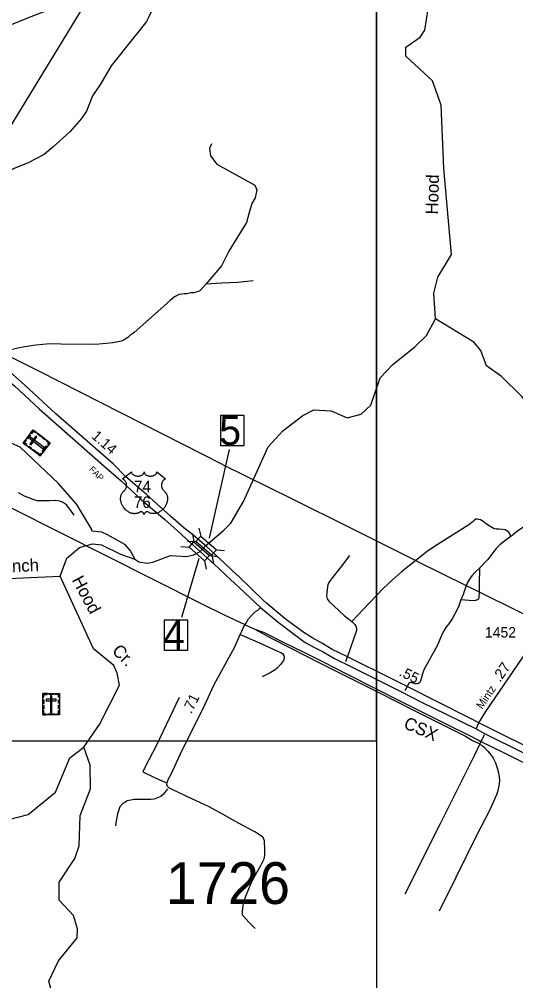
# Model space of a CAD drawing. Extents: x 2225501 to 2309677, y 165449 to 227696.
# Drawn here: x 2261977 to 2267922, y 188364 to 199877 of the extents above; entities that cross this region are included whole.
import ezdxf

# ---------------------------------------------------------------- set-up
doc = ezdxf.new("R2010")
doc.units = 0
for name, color, linetype in [('Black Area Fill Shapes', 7, 'Continuous'), ('E_RDY_CMT_EOP', 7, 'Continuous'), ('MARK ENDS WORD SYMBOL CELL', 7, 'Continuous'), ('Old_Level_3', 7, 'Continuous'), ('Old_Level_33', 7, 'Continuous'), ('Old_Level_41', 7, 'Continuous'), ('Old_Level_46', 7, 'Continuous'), ('P_HYD_Ditch_Flow_Line', 7, 'Continuous'), ('P_HYD_Endwall_838_01_48_Dia_Single_CELL', 7, 'Continuous'), ('P_HYD_Pipe_Flowable_Fill', 7, 'Continuous'), ('P_HYD_Pipe_Pipe_Removal', 7, 'Continuous'), ('P_HYD_RIP_RAP_LABEL', 7, 'Continuous'), ('P_HYD_RipRap_Pad_876_02_18in_Outlet_With_Ditch-Top_CELL', 7, 'Continuous'), ('P_HYD_RipRap_Pad_876_02_36in_Outlet_With_Ditch-Top_CELL', 7, 'Continuous'), ('P_HYD_RipRap_Pad_876_02_36in_Outlet_With_Ditch_CELL', 7, 'Continuous'), ('P_RDY_Dimension_Text', 7, 'Continuous'), ('Prop Mkg Solid Yellow Edge Line', 7, 'Continuous'), ('Prop Support', 7, 'Continuous'), ('Raster_Level_0', 7, 'Continuous'), ('Scratch_Level_1', 7, 'Continuous'), ('Scratch_Level_2', 7, 'Continuous'), ('Typical Terminator CELL', 7, 'Continuous')]:
    doc.layers.add(name, color=color, linetype=linetype)

msp = doc.modelspace()

# ---------------------------------------------------------------- linework, layer by layer
at = {"layer": 'Black Area Fill Shapes'}
for p, q in [((2267328, 193098), (2267482, 193022)), ((2264683, 192627), (2264797, 192573))]:
    msp.add_line(p, q, dxfattribs=at)
for points in [[(2262843, 200185), (2262115, 199905), (2260829, 199388), (2259311, 198774), (2259155, 198714)], [(2264419, 194543), (2262221, 195661), (2261765, 195888)], [(2264683, 192627), (2264436, 192743), (2264161, 192876), (2259628, 195156)], [(2264420, 194540), (2265246, 194134), (2265934, 193792), (2266724, 193397)], [(2266724, 193397), (2266754, 193381), (2267328, 193098)], [(2267482, 193022), (2267541, 192993), (2268273, 192629)], [(2264797, 192573), (2265002, 192462), (2265244, 192337), (2265570, 192172), (2265890, 192010), (2266276, 191818), (2266712, 191596), (2267153, 191375), (2267318, 191291), (2267404, 191240), (2267491, 191200)], [(2267491, 191200), (2267492, 191199), (2267519, 191182), (2267539, 191165), (2267588, 191112), (2267623, 191070), (2267651, 191031), (2267679, 190973), (2267700, 190913), (2267715, 190855), (2267724, 190801), (2267726, 190765), (2267723, 190722), (2267717, 190683), (2267707, 190641), (2267694, 190599), (2267676, 190553), (2267644, 190481), (2267610, 190412), (2267448, 190094), (2267204, 189599), (2267004, 189199)]]:
    msp.add_lwpolyline(points, dxfattribs=at)
at = {"layer": 'Old_Level_3'}
for p, q in [((2265887, 192195), (2265883, 192183)), ((2265906, 192248), (2265887, 192195)), ((2266601, 191851), (2266593, 191838)), ((2266627, 191897), (2266601, 191851)), ((2267514, 191249), (2267505, 191230)), ((2267539, 191301), (2267514, 191249)), ((2267543, 191310), (2267539, 191301)), ((2267505, 191230), (2267491, 191200))]:
    msp.add_line(p, q, dxfattribs=at)
for points in [[(2264023, 200510), (2263878, 200419), (2263792, 200372), (2263758, 200346), (2263715, 200289), (2263654, 200179), (2263615, 200085), (2263530, 199908), (2263499, 199852), (2263428, 199760)], [(2263428, 199760), (2263330, 199633), (2263077, 199319), (2262951, 199100), (2262856, 198961), (2262782, 198776), (2262724, 198690), (2262584, 198529), (2262379, 198345), (2262276, 198256), (2262075, 198153), (2261923, 198094), (2261854, 198057), (2261784, 198017), (2261729, 197970), (2261689, 197924), (2261620, 197799), (2261558, 197711)], [(2264279, 198386), (2264256, 198328), (2264267, 198240), (2264343, 198141), (2264797, 197891), (2264820, 197833), (2264802, 197740), (2264762, 197670), (2264727, 197548), (2264698, 197443), (2264488, 197100), (2264398, 196924), (2264214, 196709)], [(2264214, 196709), (2264139, 196626), (2264123, 196618), (2264069, 196600), (2264033, 196600), (2263983, 196589), (2263955, 196589), (2263893, 196580), (2263837, 196552), (2263786, 196511), (2263351, 196124), (2263301, 196090), (2263277, 196068), (2263232, 196037), (2263200, 196021), (2263098, 196002), (2262894, 195982), (2262476, 195985), (2262345, 195990), (2262175, 195976), (2262045, 195955), (2261961, 195939), (2261835, 195908), (2261765, 195888)], [(2264214, 196709), (2264404, 196720), (2264593, 196728), (2264777, 196749)], [(2262635, 193941), (2262570, 194028), (2262542, 194062), (2262494, 194096), (2262458, 194108), (2262414, 194113), (2262338, 194109), (2262192, 194111), (2262144, 194127), (2262039, 194168), (2261967, 194206)], [(2267863, 193685), (2267848, 193725), (2267832, 193743), (2267816, 193753), (2267796, 193762), (2267765, 193767), (2267723, 193771), (2267687, 193770), (2267665, 193774), (2267595, 193816), (2267521, 193870), (2267498, 193885), (2267459, 193890), (2267445, 193890), (2267427, 193881), (2267410, 193863), (2267361, 193822), (2266947, 193563), (2266860, 193505), (2266724, 193397)], [(2268161, 193870), (2268092, 193839), (2268007, 193792), (2267942, 193749), (2267863, 193685)], [(2267863, 193685), (2267806, 193644), (2267733, 193585), (2267687, 193540), (2267584, 193406), (2267486, 193303)], [(2265933, 193458), (2265821, 193309), (2265710, 193171), (2265688, 193138), (2265673, 193107), (2265662, 193050), (2265655, 192976), (2265658, 192954), (2265664, 192937), (2265682, 192911), (2265869, 192738), (2265961, 192666)], [(2266724, 193397), (2266552, 193260), (2266446, 193166), (2266334, 193062), (2266094, 192810), (2265961, 192666)], [(2267486, 193303), (2267434, 193255), (2267395, 193212), (2267368, 193172), (2267344, 193132), (2267328, 193098)], [(2267486, 193303), (2267485, 193120), (2267482, 193022)], [(2267328, 193098), (2267322, 193085), (2267291, 192991), (2267264, 192925)], [(2267482, 193022), (2267480, 192949), (2267476, 192932), (2267462, 192924), (2267438, 192918), (2267412, 192915), (2267264, 192925)], [(2267264, 192925), (2267239, 192854), (2267213, 192794), (2267162, 192697), (2267129, 192648), (2267086, 192593), (2267061, 192555), (2267039, 192517), (2266986, 192384), (2266821, 192087), (2266804, 192041), (2266781, 191952), (2266773, 191936), (2266756, 191922), (2266740, 191920), (2266718, 191921), (2266666, 191936), (2266646, 191930), (2266627, 191897)], [(2265961, 192666), (2265993, 192632), (2266008, 192609), (2266014, 192587), (2266014, 192559), (2265906, 192248)], [(2264621, 192512), (2264853, 192412), (2265069, 192310), (2265110, 192294), (2265129, 192281), (2265143, 192259), (2265150, 192240), (2265150, 192228), (2265139, 192200), (2265106, 192153), (2265070, 192110), (2265041, 192087), (2264982, 192051), (2264886, 192005)], [(2263892, 191754), (2263619, 191187), (2263482, 190919), (2263456, 190867), (2263598, 190797), (2263733, 190739)], [(2267491, 191200), (2267423, 191057), (2267243, 190700), (2267017, 190242), (2266592, 189401)], [(2263751, 190661), (2263704, 190599), (2263672, 190571), (2263592, 190538), (2263554, 190536), (2263352, 190534), (2263271, 190520), (2263243, 190497), (2263219, 190487), (2263181, 190447), (2263152, 190363), (2263137, 190279), (2263131, 190221)], [(2264800, 188991), (2264728, 189062), (2264651, 189149), (2264651, 189192), (2264654, 189230), (2264663, 189294), (2264689, 189378), (2264733, 189486), (2264770, 189568), (2264869, 189745), (2264910, 189824), (2264916, 189870), (2264916, 189937), (2264914, 190040)]]:
    msp.add_lwpolyline(points, dxfattribs=at)
at = {"layer": 'Old_Level_33'}
for points in [[(2264914, 190040), (2264896, 190079), (2264878, 190095), (2264799, 190147), (2264557, 190275), (2264456, 190335), (2264250, 190448), (2264045, 190544), (2263808, 190654), (2263770, 190674), (2263751, 190691), (2263746, 190716), (2263750, 190738), (2263765, 190781), (2263796, 190839), (2263905, 191073), (2264198, 191667), (2264310, 191912), (2264441, 192153), (2264557, 192363), (2264621, 192512), (2264643, 192551), (2264668, 192606), (2264688, 192643), (2264723, 192696), (2264761, 192741), (2264807, 192785), (2264833, 192803), (2264867, 192835)], [(2267478, 191453), (2267564, 191588), (2268227, 192557), (2268238, 192574), (2268262, 192614), (2268273, 192629)], [(2267446, 191381), (2267478, 191453)]]:
    msp.add_lwpolyline(points, dxfattribs=at)
at = {"layer": 'Old_Level_41'}
msp.add_lwpolyline([(2264797, 192573), (2264855, 192556), (2264881, 192548), (2264917, 192531), (2265153, 192412), (2265368, 192306), (2265614, 192185), (2265897, 192040), (2266233, 191868), (2266549, 191708), (2266815, 191575), (2267126, 191420), (2267344, 191313), (2267483, 191241), (2267505, 191230), (2267760, 191104), (2268233, 190867)], dxfattribs=at)
at = {"layer": 'Old_Level_46'}
for points in [[(2264218, 193562), (2264055, 193705), (2263947, 193788), (2263787, 193927), (2263500, 194185), (2263249, 194403), (2263106, 194549), (2262416, 195153), (2262043, 195497), (2261860, 195659), (2261615, 195862), (2261559, 195902), (2261462, 195966), (2261288, 196067), (2261080, 196147), (2260943, 196189), (2260766, 196223), (2260631, 196248), (2260380, 196284), (2260177, 196311)], [(2260129, 196210), (2260183, 196202), (2260349, 196183), (2260525, 196155), (2260708, 196126), (2260872, 196091), (2261053, 196047), (2261233, 195984), (2261408, 195889), (2261522, 195818), (2261758, 195618), (2261921, 195486), (2262216, 195211), (2262991, 194529), (2263196, 194349), (2263442, 194123), (2263721, 193887), (2263873, 193751), (2263970, 193660), (2264145, 193503)], [(2264938, 192884), (2264897, 192923), (2264609, 193200), (2264531, 193274), (2264434, 193364), (2264218, 193562)], [(2264145, 193503), (2264361, 193306), (2264453, 193218), (2264611, 193074), (2264867, 192835)], [(2267478, 191453), (2267395, 191496), (2266944, 191725), (2266686, 191854), (2266469, 191962), (2265892, 192249), (2265723, 192332), (2265608, 192402), (2265491, 192466), (2265386, 192535), (2265268, 192617), (2265159, 192696), (2264938, 192884)], [(2264867, 192835), (2265076, 192657), (2265257, 192521), (2265401, 192416), (2265514, 192355), (2265616, 192302), (2265753, 192223), (2265947, 192127), (2266537, 191830), (2266800, 191697), (2267088, 191555), (2267446, 191381)], [(2267446, 191381), (2267549, 191323), (2268023, 191089), (2268853, 190675), (2269145, 190533), (2269376, 190413), (2269867, 190171), (2270152, 190029), (2270264, 189970), (2270773, 189716), (2271345, 189429), (2271616, 189294), (2272532, 188836)], [(2272571, 188913), (2271872, 189261), (2271516, 189439), (2271065, 189667), (2270762, 189820), (2270313, 190042), (2269837, 190283), (2269384, 190510), (2268843, 190777), (2268116, 191138), (2267673, 191357), (2267478, 191453)]]:
    msp.add_lwpolyline(points, dxfattribs=at)
at = {"layer": 'P_HYD_Endwall_838_01_48_Dia_Single_CELL'}
msp.add_lwpolyline([(2262842, 200192), (2261366, 197773), (2261577, 197678), (2260763, 196442), (2260802, 196385), (2260862, 196311), (2260866, 196277), (2260818, 196274), (2260687, 196341), (2260590, 196381), (2260485, 196410), (2260197, 196443), (2259793, 196486), (2259225, 196552), (2258394, 196652), (2257678, 196732), (2257280, 196779), (2256996, 196809), (2256790, 196892), (2256494, 197039)], dxfattribs=at)
at = {"layer": 'P_HYD_Pipe_Pipe_Removal'}
for points in [[(2243856, 191238), (2266254, 191238), (2266254, 223234), (2243856, 223234)], [(2266254, 165449), (2309677, 165449), (2309677, 209697), (2266254, 209697)]]:
    msp.add_lwpolyline(points, close=True, dxfattribs=at)
at = {"layer": 'P_HYD_RIP_RAP_LABEL'}
for p, q in [((2264254, 193662), (2264494, 194727)), ((2264129, 193422), (2263920, 192715))]:
    msp.add_line(p, q, dxfattribs=at)
for points in [[(2264390, 195136), (2264665, 195136), (2264665, 194768), (2264390, 194768)], [(2263717, 192686), (2263993, 192686), (2263993, 192318), (2263717, 192318)]]:
    msp.add_lwpolyline(points, close=True, dxfattribs=at)
at = {"layer": 'P_HYD_RipRap_Pad_876_02_18in_Outlet_With_Ditch-Top_CELL'}
msp.add_lwpolyline([(2263320, 194458), (2263320, 194454), (2263321, 194449), (2263322, 194446), (2263324, 194441), (2263328, 194435), (2263334, 194429), (2263340, 194424), (2263344, 194421), (2263352, 194417), (2263360, 194413), (2263369, 194411), (2263378, 194409), (2263389, 194408), (2263399, 194408), (2263410, 194408), (2263422, 194411), (2263427, 194412), (2263433, 194414), (2263439, 194417), (2263446, 194420), (2263451, 194423), (2263455, 194426), (2263460, 194432), (2263465, 194437), (2263467, 194440), (2263468, 194443), (2263471, 194450), (2263471, 194453), (2263472, 194459), (2263472, 194454), (2263472, 194450), (2263473, 194447), (2263475, 194444), (2263477, 194440), (2263479, 194436), (2263484, 194430), (2263487, 194428), (2263490, 194425), (2263497, 194420), (2263505, 194416), (2263510, 194414), (2263514, 194413), (2263519, 194411), (2263525, 194410), (2263530, 194409), (2263536, 194408), (2263542, 194408), (2263546, 194408), (2263552, 194408), (2263558, 194408), (2263563, 194409), (2263569, 194410), (2263574, 194411), (2263580, 194412), (2263586, 194414), (2263591, 194417), (2263598, 194420), (2263603, 194423), (2263607, 194427), (2263612, 194431), (2263616, 194436), (2263619, 194440), (2263620, 194443), (2263622, 194447), (2263623, 194452), (2263624, 194455), (2263624, 194459), (2263730, 194374), (2263727, 194373), (2263722, 194370), (2263717, 194367), (2263710, 194362), (2263707, 194359), (2263704, 194357), (2263701, 194353), (2263698, 194350), (2263695, 194346), (2263692, 194342), (2263690, 194337), (2263688, 194333), (2263684, 194325), (2263683, 194319), (2263682, 194315), (2263680, 194305), (2263680, 194301), (2263680, 194296), (2263680, 194291), (2263681, 194287), (2263682, 194282), (2263682, 194278), (2263684, 194273), (2263686, 194267), (2263688, 194261), (2263693, 194252), (2263699, 194243), (2263704, 194237), (2263708, 194233), (2263714, 194227), (2263718, 194224), (2263722, 194220), (2263729, 194212), (2263731, 194209), (2263734, 194205), (2263737, 194200), (2263739, 194196), (2263741, 194192), (2263745, 194183), (2263748, 194174), (2263749, 194169), (2263751, 194159), (2263752, 194154), (2263752, 194144), (2263753, 194131), (2263752, 194120), (2263749, 194106), (2263748, 194098), (2263745, 194088), (2263742, 194080), (2263737, 194068), (2263733, 194059), (2263727, 194049), (2263723, 194043), (2263719, 194036), (2263713, 194028), (2263707, 194020), (2263699, 194012), (2263693, 194005), (2263684, 193998), (2263679, 193994), (2263672, 193988), (2263662, 193982), (2263653, 193976), (2263645, 193972), (2263637, 193969), (2263628, 193965), (2263612, 193961), (2263606, 193960), (2263600, 193959), (2263593, 193958), (2263587, 193958), (2263579, 193958), (2263571, 193958), (2263563, 193960), (2263555, 193961), (2263546, 193964), (2263539, 193967), (2263531, 193971), (2263518, 193979), (2263514, 193981), (2263512, 193981), (2263507, 193982), (2263502, 193981), (2263497, 193979), (2263494, 193977), (2263490, 193975), (2263487, 193972), (2263484, 193969), (2263481, 193966), (2263479, 193964), (2263475, 193958), (2263474, 193955), (2263473, 193951), (2263471, 193946), (2263470, 193953), (2263468, 193957), (2263466, 193961), (2263463, 193964), (2263460, 193969), (2263456, 193972), (2263452, 193975), (2263448, 193978), (2263445, 193979), (2263441, 193981), (2263438, 193982), (2263434, 193982), (2263432, 193982), (2263428, 193981), (2263423, 193977), (2263419, 193974), (2263414, 193971), (2263408, 193968), (2263404, 193966), (2263399, 193964), (2263393, 193962), (2263386, 193960), (2263379, 193959), (2263373, 193958), (2263367, 193958), (2263361, 193957), (2263355, 193957), (2263350, 193958), (2263343, 193958), (2263335, 193960), (2263329, 193961), (2263322, 193963), (2263314, 193965), (2263307, 193968), (2263297, 193972), (2263290, 193976), (2263280, 193982), (2263267, 193991), (2263258, 193998), (2263251, 194004), (2263241, 194015), (2263235, 194021), (2263226, 194033), (2263220, 194042), (2263216, 194049), (2263210, 194059), (2263207, 194065), (2263203, 194075), (2263200, 194083), (2263197, 194092), (2263196, 194097), (2263194, 194106), (2263193, 194112), (2263191, 194121), (2263191, 194131), (2263191, 194139), (2263191, 194146), (2263192, 194155), (2263193, 194163), (2263195, 194171), (2263196, 194177), (2263199, 194183), (2263202, 194191), (2263205, 194198), (2263208, 194203), (2263213, 194210), (2263217, 194215), (2263222, 194221), (2263228, 194226), (2263233, 194231), (2263239, 194237), (2263242, 194240), (2263246, 194245), (2263249, 194250), (2263252, 194254), (2263255, 194260), (2263257, 194265), (2263259, 194272), (2263261, 194277), (2263262, 194284), (2263263, 194290), (2263263, 194297), (2263263, 194304), (2263262, 194311), (2263261, 194318), (2263259, 194324), (2263256, 194331), (2263254, 194336), (2263250, 194343), (2263245, 194350), (2263241, 194355), (2263236, 194360), (2263231, 194363), (2263227, 194366), (2263222, 194370), (2263217, 194372), (2263213, 194374)], close=True, dxfattribs=at)
at = {"layer": 'P_HYD_RipRap_Pad_876_02_36in_Outlet_With_Ditch-Top_CELL'}
msp.add_lwpolyline([(2262842, 200192), (2261366, 197773), (2261577, 197678), (2260763, 196442), (2260802, 196385), (2260862, 196311), (2260866, 196277), (2260818, 196274), (2260687, 196341), (2260590, 196381), (2260485, 196410), (2260197, 196443), (2259793, 196486), (2259225, 196552), (2258394, 196652), (2257678, 196732), (2257280, 196779), (2256996, 196809), (2256790, 196892), (2256494, 197039)], dxfattribs=at)
at = {"layer": 'P_HYD_RipRap_Pad_876_02_36in_Outlet_With_Ditch_CELL'}
for p, q in [((2264129, 193785), (2264150, 193687)), ((2264050, 193719), (2264069, 193621)), ((2263912, 193564), (2264011, 193556)), ((2263993, 193629), (2264093, 193622)), ((2264254, 193455), (2264353, 193446)), ((2264281, 193460), (2264302, 193362)), ((2264337, 193524), (2264436, 193517)), ((2264197, 193392), (2264217, 193294))]:
    msp.add_line(p, q, dxfattribs=at)
for points in [[(2264150, 193687), (2264337, 193525), (2264280, 193459), (2264093, 193622)], [(2264069, 193621), (2264254, 193455), (2264196, 193391), (2264011, 193556)]]:
    msp.add_lwpolyline(points, close=True, dxfattribs=at)
at = {"layer": 'Prop Mkg Solid Yellow Edge Line'}
for points in [[(2262025, 194802), (2262145, 194961), (2262348, 194807), (2262228, 194648)], [(2262179, 194935), (2262172, 194926), (2262147, 194945), (2262122, 194913), (2262113, 194919), (2262145, 194961)], [(2262059, 194776), (2262066, 194785), (2262040, 194804), (2262065, 194837), (2262056, 194843), (2262025, 194802)], [(2262069, 194861), (2262100, 194902), (2262110, 194895), (2262078, 194854)], [(2262114, 194871), (2262102, 194856), (2262264, 194734), (2262275, 194749)], [(2262103, 194793), (2262118, 194782), (2262189, 194876), (2262174, 194887)], [(2262231, 194881), (2262196, 194908), (2262203, 194917), (2262238, 194891)], [(2262283, 194842), (2262249, 194868), (2262256, 194877), (2262290, 194851)], [(2262328, 194781), (2262319, 194788), (2262332, 194805), (2262300, 194830), (2262306, 194838), (2262348, 194807)], [(2262118, 194731), (2262084, 194757), (2262091, 194766), (2262125, 194740)], [(2262172, 194691), (2262137, 194717), (2262144, 194726), (2262179, 194700)], [(2262248, 194675), (2262238, 194682), (2262225, 194664), (2262193, 194689), (2262186, 194680), (2262228, 194648)], [(2262253, 194701), (2262304, 194769), (2262313, 194762), (2262262, 194694)], [(2262260, 191803), (2262459, 191803), (2262459, 191549), (2262260, 191549)], [(2262260, 191760), (2262272, 191760), (2262272, 191792), (2262312, 191792), (2262312, 191803), (2262260, 191803)], [(2262260, 191686), (2262260, 191729), (2262272, 191729), (2262272, 191686)], [(2262301, 191735), (2262301, 191717), (2262419, 191717), (2262419, 191735)], [(2262334, 191803), (2262386, 191803), (2262386, 191792), (2262334, 191792)], [(2262369, 191774), (2262351, 191774), (2262351, 191571), (2262369, 191571)], [(2262459, 191760), (2262448, 191760), (2262448, 191792), (2262407, 191792), (2262407, 191803), (2262459, 191803)], [(2262448, 191687), (2262448, 191730), (2262459, 191730), (2262459, 191687)], [(2262260, 191619), (2262260, 191662), (2262272, 191662), (2262272, 191619)], [(2262293, 191549), (2262293, 191560), (2262271, 191560), (2262271, 191601), (2262260, 191601), (2262260, 191549)], [(2262426, 191549), (2262426, 191560), (2262448, 191560), (2262448, 191601), (2262459, 191601), (2262459, 191549)], [(2262448, 191621), (2262448, 191664), (2262459, 191664), (2262459, 191621)], [(2262318, 191560), (2262403, 191560), (2262403, 191549), (2262318, 191549)]]:
    msp.add_lwpolyline(points, close=True, dxfattribs=at)
at = {"layer": 'Prop Support'}
msp.add_lwpolyline([(2262848, 193750), (2262845, 193768), (2262668, 194067), (2262449, 194317), (2261987, 194752), (2261879, 194803), (2261671, 194752), (2261464, 194641), (2261199, 194446), (2261099, 194422), (2260723, 194501), (2260624, 194467), (2260599, 194425), (2260620, 193900), (2260581, 193625), (2260498, 193525), (2259731, 193602)], dxfattribs=at)
at = {"layer": 'Typical Terminator CELL'}
for points in [[(2266959, 196289), (2266940, 196598), (2266988, 196790), (2267152, 197059), (2267059, 198091), (2267027, 198849), (2266924, 199140), (2266605, 199435), (2266604, 199543), (2266778, 199661), (2266835, 199745), (2266874, 200003), (2266932, 200071), (2267330, 200293), (2267502, 200601), (2267570, 201312)], [(2264427, 193761), (2264509, 193844), (2264664, 194103), (2264958, 194757), (2265131, 194947), (2265371, 195132), (2265504, 195202), (2265712, 195188), (2265904, 195106), (2266071, 195148), (2266186, 195258), (2266300, 195583), (2266448, 195745), (2266713, 195956), (2266853, 196091), (2266959, 196289)], [(2268914, 193968), (2268795, 194190), (2268280, 194918), (2268145, 195167), (2267993, 195360), (2267749, 195598), (2267573, 195729), (2267505, 195911), (2267420, 196011), (2266959, 196289)], [(2262848, 193750), (2262961, 193739), (2263028, 193706), (2263238, 193591), (2263309, 193508), (2263362, 193411)], [(2263362, 193411), (2263410, 193381), (2263509, 193365), (2263578, 193375), (2263788, 193455), (2263981, 193444), (2264066, 193463), (2264145, 193503), (2264176, 193537), (2264209, 193573), (2264427, 193761)], [(2262467, 193208), (2262548, 193426), (2262697, 193551), (2262855, 193594), (2262961, 193582), (2263191, 193473), (2263362, 193411)], [(2257978, 192055), (2258618, 192243), (2258999, 192439), (2259190, 192491), (2260148, 192574), (2260289, 192607), (2260513, 192751), (2260678, 192928), (2260976, 193106), (2261309, 193158), (2262467, 193208)], [(2262750, 191162), (2262939, 191431), (2263177, 191905), (2263151, 192046), (2263108, 192139), (2262865, 192337), (2262467, 193208)], [(2261492, 190203), (2262082, 190355), (2262413, 190624), (2262584, 191034), (2262750, 191162)], [(2263732, 186131), (2263723, 186246), (2263689, 186270), (2263637, 186536), (2263375, 187033), (2263375, 187076), (2263129, 187533), (2263135, 187881), (2263076, 187964), (2262450, 188134), (2262366, 188227), (2262331, 188359), (2262446, 188603), (2262669, 188877), (2262676, 188986), (2262625, 189144), (2262457, 189328), (2262455, 189544), (2262644, 189829), (2262693, 189979), (2262707, 190343), (2262829, 190662), (2262827, 190944), (2262750, 191162)]]:
    msp.add_lwpolyline(points, dxfattribs=at)

# ---------------------------------------------------------------- texts
at = {"layer": 'E_RDY_CMT_EOP'}
for s, height, p in [('1452', 125, (2267553, 192474)), ('1726', 500, (2263732, 189284))]:
    msp.add_text(s, height=height, dxfattribs=at).set_placement(p)
at = {"layer": 'MARK ENDS WORD SYMBOL CELL'}
msp.add_text('Mintz', height=95, rotation=55.6168, dxfattribs=at).set_placement((2267519, 191610))
at = {"layer": 'P_HYD_Ditch_Flow_Line'}
for s, p in [('74', (2263350, 194214)), ('76', (2263348, 194026))]:
    msp.add_text(s, height=137.5, dxfattribs=at).set_placement(p)
at = {"layer": 'P_HYD_Pipe_Flowable_Fill'}
msp.add_text('CSX', height=150, rotation=336.7254, dxfattribs=at).set_placement((2266568, 191394))
at = {"layer": 'P_HYD_RIP_RAP_LABEL'}
for s, p in [('5', (2264372, 194780)), ('4', (2263699, 192329))]:
    msp.add_text(s, height=350, dxfattribs=at).set_placement(p)
at = {"layer": 'P_RDY_Dimension_Text'}
for s, rotation, p in [('.27', 55.6168, (2267734, 191930)), ('.71', 63.7497, (2264037, 191553))]:
    msp.add_text(s, height=125, rotation=rotation, dxfattribs=at).set_placement(p)
at = {"layer": 'Raster_Level_0'}
for s, rotation, p in [('1.14', 318.7941, (2262833, 194872)), ('.55', 333.5867, (2266516, 192023))]:
    msp.add_text(s, height=125, rotation=rotation, dxfattribs=at).set_placement(p)
at = {"layer": 'Scratch_Level_1'}
for s, rotation, p in [('Hood', 88.5309, (2266991, 197538)), ('Branch', 2.4545, (2261581, 193242)), ('Hood', 298.1915, (2262603, 193164)), ('Cr.', 314.8585, (2263078, 192304))]:
    msp.add_text(s, height=150, rotation=rotation, dxfattribs=at).set_placement(p)
at = {"layer": 'Scratch_Level_2'}
msp.add_text('FAP', height=75, rotation=313.8969, dxfattribs=at).set_placement((2262808, 194482))

doc.saveas('drawing.dxf')
